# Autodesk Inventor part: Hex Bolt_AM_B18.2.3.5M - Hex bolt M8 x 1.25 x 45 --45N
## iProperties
Shininess: 64.0
Length Units: 11269
Angle Units: 11279
Time Units: 11290
Mass Units: 11283
Length Display Precision: 3
Angle Display Precision: 2
Compacted: True
Part Number: Hex Bolt_AM_B18.2.3.5M - Hex bolt M8 x 1.25 x 45 --45N
Document SubType Name: Modeling
Created: 2006-11
Material: Par défaut
Designer: profs_sti
Density: 0.0
Volumn: 0.0
Area: 0.0
PropertySet Name: Model Information
Control State: 0
Master: False
Checked Out: False
Author: profs_sti
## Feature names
1. Base1
